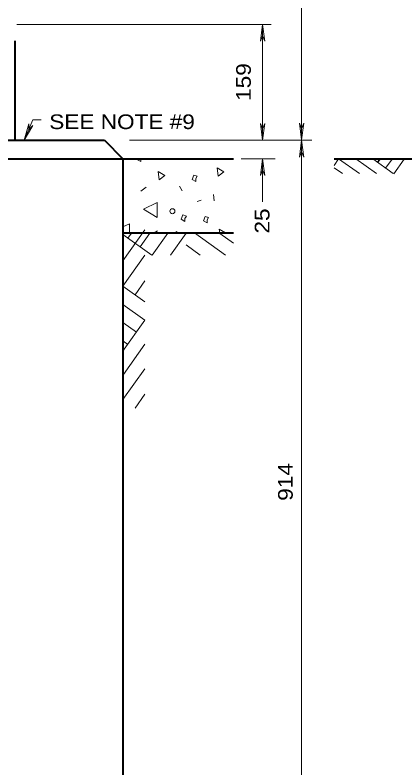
# Model space of a CAD drawing. Extents: x 312583 to 312854, y 144419 to 144597.
# Drawn here: x 312669.46 to 312689.63, y 144489.1 to 144528.04 of the extents above; entities that cross this region are included whole.
import ezdxf

# ---------------------------------------------------------------- set-up
doc = ezdxf.new("R2010")
doc.units = 0
doc.header["$LTSCALE"] = 0.3
doc.layers.add('1', color=7, linetype='Continuous', lineweight=25)
doc.layers.add('2', color=7, linetype='Continuous', lineweight=13)

msp = doc.modelspace()

# ---------------------------------------------------------------- linework, layer by layer
at = {"layer": '1', "lineweight": 40}
for p, q in [((312669.4601, 144521.5664), (312669.4601, 144526.703)), ((312635.7498, 144521.5664), (312674.0831, 144521.5664)), ((312674.0831, 144521.5664), (312675.0415, 144520.608)), ((312666.3475, 144520.608), (312680.7608, 144520.608)), ((312675.0415, 144520.608), (312675.0415, 144487.0664)), ((312685.9665, 144520.608), (312690.6048, 144520.608)), ((312675.0415, 144516.7747), (312680.7608, 144516.7747))]:
    msp.add_line(p, q, dxfattribs=at)
at = {"layer": '1', "lineweight": 13}
for p, q in [((312686.2041, 144520.608), (312685.9665, 144520.263)), ((312687.2775, 144519.8414), (312686.2041, 144520.608)), ((312688.1591, 144519.8414), (312687.0858, 144520.608)), ((312689.0331, 144519.8414), (312687.9675, 144520.608)), ((312688.9718, 144520.5927), (312688.6345, 144520.1327)), ((312689.5928, 144520.5927), (312689.0561, 144519.8337)), ((312686.3958, 144519.8414), (312685.9665, 144520.148))]:
    msp.add_line(p, q, dxfattribs=at)
at = {"layer": '1', "lineweight": 35}
msp.add_line((312688.3431, 144520.5927), (312688.2205, 144520.424), dxfattribs=at)
at = {"layer": '2'}
for p, q in [((312669.5521, 144527.554), (312682.7081, 144527.554)), ((312682.2711, 144527.554), (312682.1638, 144526.6877)), ((312682.2711, 144521.5664), (312682.2711, 144527.554)), ((312682.2711, 144527.554), (312682.3785, 144526.6877)), ((312682.1638, 144526.6877), (312682.2711, 144526.9637)), ((312682.3785, 144526.6877), (312682.2711, 144526.9637)), ((312670.3878, 144522.6167), (312669.9278, 144521.574)), ((312670.3878, 144522.6167), (312670.8171, 144522.6167)), ((312669.9278, 144521.574), (312670.1808, 144522.4097)), ((312669.9278, 144521.574), (312670.3725, 144522.3254)), ((312670.1808, 144522.4097), (312670.1655, 144522.1107)), ((312670.3725, 144522.3254), (312670.1655, 144522.1107)), ((312682.1638, 144522.4327), (312682.2711, 144522.1567)), ((312682.2711, 144521.5664), (312682.1638, 144522.4327)), ((312682.3785, 144522.4327), (312682.2711, 144522.1567)), ((312682.2711, 144521.5664), (312682.3785, 144522.4327)), ((312684.1801, 144522.4557), (312684.2875, 144522.1797)), ((312684.2875, 144521.5894), (312684.1801, 144522.4557)), ((312684.3948, 144522.4557), (312684.2875, 144522.1797)), ((312684.2875, 144521.5894), (312684.3948, 144522.4557)), ((312684.2875, 144521.5664), (312684.1801, 144520.7)), ((312684.2875, 144521.5664), (312684.3948, 144520.7)), ((312684.1801, 144520.7), (312684.2875, 144520.976)), ((312684.3948, 144520.7), (312684.2875, 144520.976)), ((312681.1671, 144520.608), (312682.9228, 144520.608)), ((312682.2711, 144520.608), (312682.1638, 144519.7417)), ((312682.2711, 144518.377), (312682.2711, 144520.608)), ((312682.2711, 144520.608), (312682.3785, 144519.7417)), ((312675.0415, 144520.24), (312675.0951, 144520.2324)), ((312682.1638, 144519.7417), (312682.2711, 144520.0177)), ((312682.3785, 144519.7417), (312682.2711, 144520.0177)), ((312676.2451, 144519.136), (312675.9691, 144518.929)), ((312677.9701, 144519.1974), (312678.1005, 144518.9444)), ((312679.7258, 144518.7604), (312679.7565, 144518.4384)), ((312678.8825, 144518.4077), (312679.0971, 144518.469)), ((312676.1838, 144516.9357), (312675.0415, 144515.3334)), ((312675.4861, 144516.7594), (312675.3021, 144516.5064)), ((312676.4291, 144516.7594), (312675.9308, 144516.0617)), ((312677.3645, 144516.7594), (312676.5518, 144515.617)), ((312676.6591, 144516.7747), (312676.8355, 144516.8744)), ((312678.3075, 144516.7594), (312677.4948, 144515.617)), ((312680.3545, 144515.6324), (312678.7521, 144516.7747)), ((312676.5288, 144515.6324), (312675.0415, 144516.6904)), ((312680.7608, 144516.2457), (312680.0631, 144516.744)), ((312679.0358, 144515.6324), (312678.3075, 144516.1537)), ((312676.1838, 144515.617), (312675.0415, 144514.0147)), ((312676.1838, 144514.2984), (312675.6701, 144513.57)), ((312675.0415, 144514.0147), (312676.1838, 144513.202)), ((312675.0415, 144513.0717), (312676.1838, 144512.259)), ((312676.1838, 144512.259), (312675.0261, 144510.6337)), ((312675.0415, 144512.1364), (312675.7391, 144511.638)), ((312675.0415, 144511.1934), (312675.2945, 144511.0094)), ((312676.1838, 144511.017), (312675.0721, 144509.453)), ((312676.1838, 144509.752), (312675.0415, 144508.1497)), ((312676.1838, 144508.4257), (312675.6701, 144507.705))]:
    msp.add_line(p, q, dxfattribs=at)
for points in [[(312684.2875, 144487.0664), (312684.2875, 144521.5894), (312684.2875, 144568.425)], [(312675.3788, 144521.5664), (312684.2261, 144521.5664), (312684.8165, 144521.5664)], [(312675.7851, 144520.608), (312675.7698, 144520.5697), (312675.9615, 144520.4624), (312675.9615, 144520.608)], [(312675.3865, 144516.7747), (312675.3865, 144517.25), (312675.0415, 144517.0814)], [(312677.9318, 144516.7747), (312677.8015, 144516.8514), (312677.8168, 144516.7747)], [(312680.3468, 144516.7747), (312680.0171, 144516.9664), (312680.0478, 144516.7747)]]:
    msp.add_lwpolyline(points, dxfattribs=at)
for points in [[(312676.9198, 144519.527), (312677.2111, 144519.7494), (312676.8585, 144519.9564)], [(312679.9711, 144519.7187), (312680.2548, 144519.941), (312679.9098, 144520.148)], [(312678.8211, 144519.5884), (312678.8901, 144519.711), (312678.7138, 144519.7647), (312678.6295, 144519.5347), (312678.8211, 144519.4274)], [(312676.8048, 144517.5797), (312676.8048, 144518.354), (312676.0995, 144518.0014)], [(312678.2461, 144517.526), (312678.3228, 144517.6487), (312678.1465, 144517.7024), (312678.0545, 144517.48), (312678.2461, 144517.3727)], [(312679.3961, 144517.4494), (312679.4651, 144517.572), (312679.2888, 144517.6257), (312679.2045, 144517.3957), (312679.3961, 144517.296)]]:
    msp.add_lwpolyline(points, close=True, dxfattribs=at)
msp.add_circle((312677.601, 144517.8974), 0.1298, dxfattribs=at)

# ---------------------------------------------------------------- texts
at = {"layer": '2', "width": 1.15}
for s, p in [('159 ', (312681.6599, 144523.6026)), ('25 ', (312682.6248, 144516.7419)), ('914 ', (312683.8285, 144502.9179))]:
    msp.add_text(s, height=0.76, rotation=90, dxfattribs=at).set_placement(p)
msp.add_text('SEE NOTE #9', height=0.76, dxfattribs=at).set_placement((312671.2286, 144522.1451))

doc.saveas('drawing.dxf')
